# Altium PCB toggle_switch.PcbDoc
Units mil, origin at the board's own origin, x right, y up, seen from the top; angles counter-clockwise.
Board outline 315 x 550 mil, 2 copper layers (Top Layer, Bottom Layer); 1 components, 0 nets, 3 pads, 0 vias.
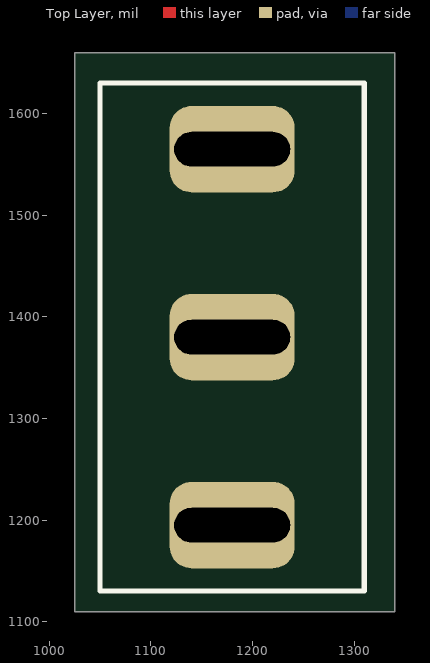
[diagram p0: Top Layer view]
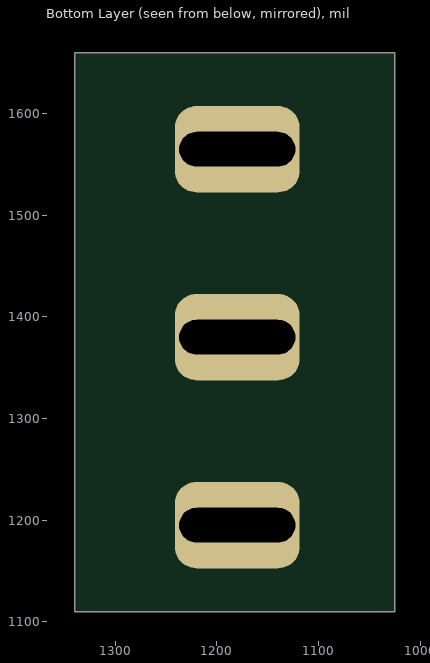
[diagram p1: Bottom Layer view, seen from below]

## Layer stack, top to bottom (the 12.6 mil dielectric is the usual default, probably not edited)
Top Solder: solder mask 0.4, Solder Resist, Dk 3.5
Top Layer: signal copper 1.4
Dielectric 1: dielectric 12.6, FR-4, Dk 4.8
Bottom Layer: signal copper 1.4
Bottom Solder: solder mask 0.4, Solder Resist, Dk 3.5

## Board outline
1025,1110 1340,1110 1340,1660 1025,1660

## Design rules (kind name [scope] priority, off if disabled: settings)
Clearance [All] p1: gap=10 ignorepadtopadclearanceinfootprint=FALSE except(0: Arc-Hole Track-Hole SMDPad-Hole THPad-Hole Via-Hole Fill-Hole Poly-Hole Region-Hole Text-Hole)
PolygonConnect [All] p1: connectstyle=Relief reliefconductorwidth=10 reliefentries=4 polygonreliefangle="90 Angle" airgapwidth=10
RoutingVias [All] p1: holewidth=28 width=50 viastyle="Through Hole" minholewidth=28 minwidth=50 maxholewidth=28 maxwidth=50
SolderMaskExpansion [All] p1: expansion=4
Width [All] p1: maxlimit=10 minlimit=10 preferedwidth=10
30 further rules are at their usual default settings.

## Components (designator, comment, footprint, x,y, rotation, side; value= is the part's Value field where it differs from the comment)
? "Comment" E101MD1AQE 1050,1130 r0 top

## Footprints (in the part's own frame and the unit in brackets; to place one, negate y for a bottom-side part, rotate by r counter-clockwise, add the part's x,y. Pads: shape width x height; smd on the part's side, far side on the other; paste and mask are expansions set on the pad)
E101MD1AQE [mil] "SWITCH TOGGLE SPDT 7.5A 125V"
  rrect50% 123x85 hole 34 slot 114 at 0 deg: 1(130,435) 2(130,250) 3(130,65)
  silkscreen extent 0,0 260,500

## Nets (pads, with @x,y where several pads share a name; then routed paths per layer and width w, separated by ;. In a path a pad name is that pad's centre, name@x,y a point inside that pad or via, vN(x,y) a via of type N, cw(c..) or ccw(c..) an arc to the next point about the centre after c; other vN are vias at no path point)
pads on no net: ?.1 ?.2 ?.3

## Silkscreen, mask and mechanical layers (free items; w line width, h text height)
Mechanical 1:
  lines w10: 1025,1110 1340,1110 1340,1655 1335,1660 1025,1660 1025,1110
